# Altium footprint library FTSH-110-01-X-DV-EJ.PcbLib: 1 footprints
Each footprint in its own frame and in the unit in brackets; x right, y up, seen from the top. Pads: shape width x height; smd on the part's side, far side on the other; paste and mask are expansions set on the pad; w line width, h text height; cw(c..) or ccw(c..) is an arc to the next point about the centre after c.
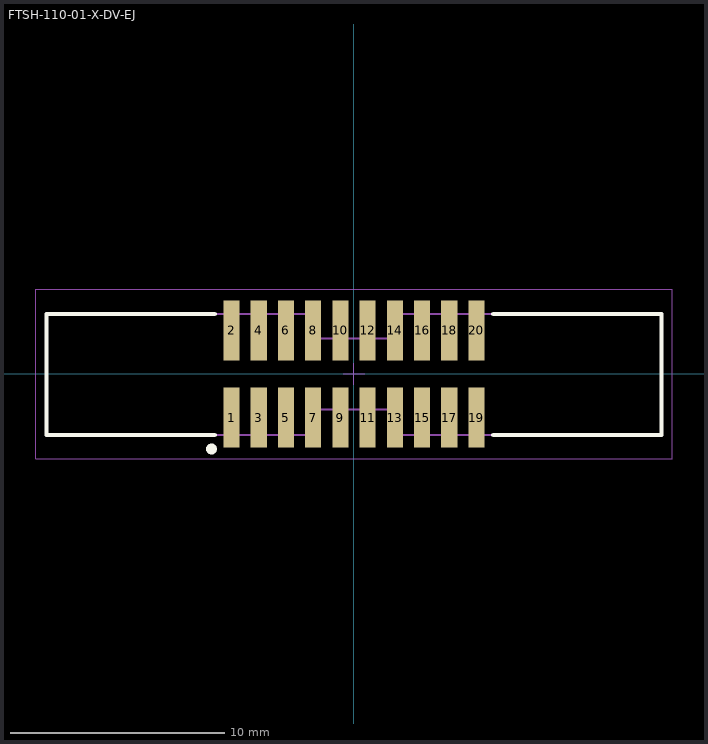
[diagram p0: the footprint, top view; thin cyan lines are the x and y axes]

## FTSH-110-01-X-DV-EJ [mm] "1.27mm pitch, 20 pin, terminal strip; vertical, double row, w/ejector shroud, SMT"
height 5.97
pads (20):
  rect 0.75x2.8 smd mask+0: 1(-5.715,-2.032) 2(-5.715,2.032) 3(-4.445,-2.032) 4(-4.445,2.032) 5(-3.175,-2.032) 6(-3.175,2.032) 7(-1.905,-2.032) 8(-1.905,2.032) 9(-0.635,-2.032) 10(-0.635,2.032) 11(0.635,-2.032) 12(0.635,2.032) 13(1.905,-2.032) 14(1.905,2.032) 15(3.175,-2.032) 16(3.175,2.032) 17(4.445,-2.032) 18(4.445,2.032) 19(5.715,-2.032) 20(5.715,2.032)
Top Overlay:
  circle w0.25: c-6.65,-3.5 r0.125
  lines w0.2: -6.5,-2.85 -14.35,-2.85 -14.35,2.8 -6.5,2.8 ; 6.5,-2.85 14.35,-2.85 14.35,2.8 6.5,2.8
Mechanical 12:
  lines w0.001: -14.35,-2.85 -14.35,2.8 -2.15,2.8 -2.15,1.651 2.15,1.651 2.15,2.8 14.35,2.8 14.35,-2.85 2.15,-2.85 2.15,-1.65 -2.15,-1.65 -2.15,-2.85 -14.35,-2.85
Mechanical 13:
  lines w0.1: -14.35,-2.85 -14.35,2.8 -2.15,2.8 -2.15,1.651 2.15,1.651 2.15,2.8 14.35,2.8 14.35,-2.85 2.15,-2.85 2.15,-1.65 -2.15,-1.65 -2.15,-2.85 -14.35,-2.85
  text ".Designator" at 0,0 h1.52
Mechanical 15:
  lines w0.05: -0.5,0 0.5,0 ; 0,-0.5 0,0.5 ; -14.85,-3.95 -14.85,3.95 14.85,3.95 14.85,-3.95 -14.85,-3.95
